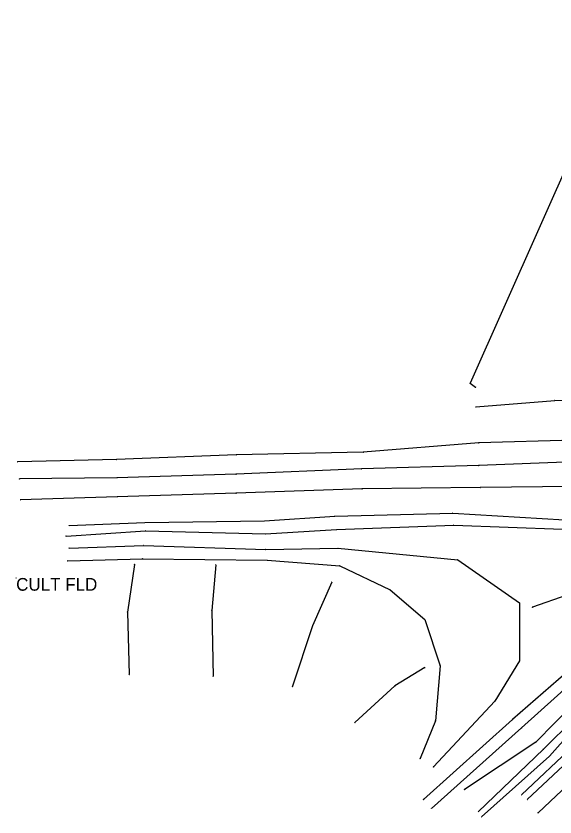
# Model space of a CAD drawing. Extents: x 1419505 to 1434054, y 1956910 to 1968644.
# Drawn here: x 1432317.2 to 1432529.3, y 1967106.7 to 1967422 of the extents above; entities that cross this region are included whole.
import ezdxf

# ---------------------------------------------------------------- set-up
doc = ezdxf.new("R2010")
doc.units = 0
for name, color, linetype in [('S_BREAKLINE', 7, 'Continuous'), ('S_DITCHLINE', 7, 'Continuous'), ('S_EDGE_PAVEMENT', 7, 'Continuous'), ('S_GRAVEL_ROAD', 7, 'Continuous'), ('S_GRD_PT_SYM', 7, 'Continuous'), ('S_MSC_PT_SYM', 7, 'Continuous'), ('S_PAVEMENT_CROWN', 7, 'Continuous'), ('S_RDW_PT_SYM', 7, 'Continuous'), ('S_SHOULDER', 7, 'Continuous'), ('S_SURVEY_TEXT_ANNOT', 7, 'Continuous')]:
    doc.layers.add(name, color=color, linetype=linetype)

msp = doc.modelspace()

# ---------------------------------------------------------------- linework, layer by layer
at = {"layer": 'S_BREAKLINE'}
for p, q in [((1432560.0563, 1967422.0191), (1432495.9372, 1967277.4358)), ((1432495.9372, 1967277.4358), (1432498.0663, 1967275.9717)), ((1432498.2003, 1967268.1522), (1432529.1903, 1967270.6804)), ((1432529.1903, 1967270.6804), (1432576.7534, 1967271.8494)), ((1432414.9679, 1967223.2913), (1432442.6717, 1967225.1514)), ((1432442.6717, 1967225.1514), (1432489.0497, 1967226.2985)), ((1432489.0497, 1967226.2985), (1432533.0896, 1967223.6753)), ((1432338.1, 1967221.4392), (1432367.8779, 1967222.6233)), ((1432367.8779, 1967222.6233), (1432414.9679, 1967223.2913)), ((1432443.3758, 1967219.8871), (1432489.4507, 1967221.5802)), ((1432489.4507, 1967221.5802), (1432532.2115, 1967219.9741)), ((1432336.8839, 1967217.3089), (1432368.1079, 1967219.3541)), ((1432368.1079, 1967219.3541), (1432415.426, 1967218.132)), ((1432415.426, 1967218.132), (1432443.3758, 1967219.8871)), ((1432338.032, 1967212.5476), (1432367.2998, 1967213.5257)), ((1432367.2998, 1967213.5257), (1432415.45, 1967212.0446)), ((1432415.45, 1967212.0446), (1432443.8868, 1967212.4766)), ((1432443.8868, 1967212.4766), (1432491.0348, 1967207.9533)), ((1432337.5179, 1967207.5113), (1432366.9238, 1967208.3894)), ((1432363.7476, 1967206.1302), (1432361.0204, 1967187.374)), ((1432366.9238, 1967208.3894), (1432416.071, 1967207.7913)), ((1432395.7667, 1967205.9642), (1432394.2956, 1967187.977)), ((1432416.071, 1967207.7913), (1432444.5708, 1967205.5362)), ((1432491.0348, 1967207.9533), (1432515.3074, 1967191.0142)), ((1432444.5708, 1967205.5362), (1432464.4411, 1967196.1946)), ((1432441.4576, 1967199.1618), (1432433.9141, 1967181.9636)), ((1432464.4411, 1967196.1946), (1432478.058, 1967184.4478)), ((1432534.0146, 1967193.9934), (1432520.4247, 1967189.2581)), ((1432515.3074, 1967191.0142), (1432515.3974, 1967168.1538)), ((1432361.0204, 1967187.374), (1432361.7465, 1967162.8484)), ((1432394.2956, 1967187.977), (1432394.7676, 1967162.0754)), ((1432478.058, 1967184.4478), (1432484.1664, 1967166.2686)), ((1432433.9141, 1967181.9636), (1432425.8576, 1967157.8041)), ((1432543.0472, 1967171.614), (1432512.6112, 1967145.0493)), ((1432515.3974, 1967168.1538), (1432505.6408, 1967152.3637)), ((1432545.1023, 1967167.8597), (1432516.1835, 1967141.784)), ((1432478.145, 1967165.5666), (1432466.2952, 1967158.2901)), ((1432484.1664, 1967166.2686), (1432482.3463, 1967144.5862)), ((1432570.1649, 1967166.6427), (1432516.1655, 1967115.4223)), ((1432552.6958, 1967159.5972), (1432527.1482, 1967130.6403)), ((1432466.2952, 1967158.2901), (1432450.5672, 1967143.9662)), ((1432505.6408, 1967152.3637), (1432481.4732, 1967126.4161)), ((1432482.3463, 1967144.5862), (1432476.2009, 1967129.7003)), ((1432512.6112, 1967145.0493), (1432477.531, 1967113.5562)), ((1432516.1835, 1967141.784), (1432480.7232, 1967110.074)), ((1432527.1482, 1967130.6403), (1432500.4474, 1967106.7658))]:
    msp.add_line(p, q, dxfattribs=at)
at = {"layer": 'S_DITCHLINE'}
for p, q in [((1432548.9296, 1967163.9905), (1432521.7968, 1967136.2097)), ((1432551.9218, 1967160.5493), (1432524.851, 1967133.4315)), ((1432521.7968, 1967136.2097), (1432493.642, 1967117.4695)), ((1432524.851, 1967133.4315), (1432499.0664, 1967108.7309))]:
    msp.add_line(p, q, dxfattribs=at)
at = {"layer": 'S_EDGE_PAVEMENT'}
msp.add_line((1432576.4614, 1967159.2652), (1432522.6489, 1967108.3919), dxfattribs=at)
at = {"layer": 'S_GRAVEL_ROAD'}
for p, q in [((1432499.3074, 1967253.9743), (1432453.8754, 1967250.3111)), ((1432541.3131, 1967255.2424), (1432499.3074, 1967253.9743)), ((1432453.8754, 1967250.3111), (1432403.8462, 1967249.317)), ((1432356.7542, 1967247.4569), (1432317.8497, 1967246.5728)), ((1432403.8462, 1967249.317), (1432356.7542, 1967247.4569)), ((1432403.8072, 1967234.126), (1432356.9852, 1967232.7219)), ((1432453.3994, 1967235.8491), (1432403.8072, 1967234.126)), ((1432499.9084, 1967236.4522), (1432453.3994, 1967235.8491)), ((1432540.563, 1967236.9162), (1432499.9084, 1967236.4522)), ((1432356.9852, 1967232.7219), (1432318.8787, 1967231.5618))]:
    msp.add_line(p, q, dxfattribs=at)
at = {"layer": 'S_GRD_PT_SYM'}
for points in [[(1432495.9372, 1967277.4358), (1432495.9372, 1967277.4858), (1432495.9372, 1967277.4358), (1432495.8872, 1967277.4358), (1432495.9372, 1967277.4358), (1432495.9372, 1967277.3858), (1432495.9372, 1967277.4358), (1432495.9872, 1967277.4358)], [(1432498.0663, 1967275.9717), (1432498.0663, 1967276.0217), (1432498.0663, 1967275.9717), (1432498.0163, 1967275.9717), (1432498.0663, 1967275.9717), (1432498.0663, 1967275.9217), (1432498.0663, 1967275.9717), (1432498.1163, 1967275.9717)], [(1432529.1903, 1967270.6804), (1432529.1903, 1967270.7304), (1432529.1903, 1967270.6804), (1432529.1403, 1967270.6804), (1432529.1903, 1967270.6804), (1432529.1903, 1967270.6304), (1432529.1903, 1967270.6804), (1432529.2403, 1967270.6804)], [(1432498.2003, 1967268.1522), (1432498.2003, 1967268.2022), (1432498.2003, 1967268.1522), (1432498.1503, 1967268.1522), (1432498.2003, 1967268.1522), (1432498.2003, 1967268.1022), (1432498.2003, 1967268.1522), (1432498.2503, 1967268.1522)], [(1432442.6717, 1967225.1514), (1432442.6717, 1967225.2014), (1432442.6717, 1967225.1514), (1432442.6217, 1967225.1514), (1432442.6717, 1967225.1514), (1432442.6717, 1967225.1014), (1432442.6717, 1967225.1514), (1432442.7217, 1967225.1514)], [(1432489.0497, 1967226.2985), (1432489.0497, 1967226.3485), (1432489.0497, 1967226.2985), (1432488.9997, 1967226.2985), (1432489.0497, 1967226.2985), (1432489.0497, 1967226.2485), (1432489.0497, 1967226.2985), (1432489.0997, 1967226.2985)], [(1432338.1, 1967221.4392), (1432338.1, 1967221.4892), (1432338.1, 1967221.4392), (1432338.05, 1967221.4392), (1432338.1, 1967221.4392), (1432338.1, 1967221.3892), (1432338.1, 1967221.4392), (1432338.15, 1967221.4392)], [(1432367.8779, 1967222.6233), (1432367.8779, 1967222.6733), (1432367.8779, 1967222.6233), (1432367.8279, 1967222.6233), (1432367.8779, 1967222.6233), (1432367.8779, 1967222.5733), (1432367.8779, 1967222.6233), (1432367.9279, 1967222.6233)], [(1432414.9679, 1967223.2913), (1432414.9679, 1967223.3413), (1432414.9679, 1967223.2913), (1432414.9179, 1967223.2913), (1432414.9679, 1967223.2913), (1432414.9679, 1967223.2413), (1432414.9679, 1967223.2913), (1432415.0179, 1967223.2913)], [(1432489.4507, 1967221.5802), (1432489.4507, 1967221.6302), (1432489.4507, 1967221.5802), (1432489.4007, 1967221.5802), (1432489.4507, 1967221.5802), (1432489.4507, 1967221.5302), (1432489.4507, 1967221.5802), (1432489.5007, 1967221.5802)], [(1432368.1079, 1967219.3541), (1432368.1079, 1967219.4041), (1432368.1079, 1967219.3541), (1432368.0579, 1967219.3541), (1432368.1079, 1967219.3541), (1432368.1079, 1967219.3041), (1432368.1079, 1967219.3541), (1432368.1579, 1967219.3541)], [(1432443.3758, 1967219.8871), (1432443.3758, 1967219.9371), (1432443.3758, 1967219.8871), (1432443.3258, 1967219.8871), (1432443.3758, 1967219.8871), (1432443.3758, 1967219.8371), (1432443.3758, 1967219.8871), (1432443.4258, 1967219.8871)], [(1432336.8839, 1967217.3089), (1432336.8839, 1967217.3589), (1432336.8839, 1967217.3089), (1432336.8339, 1967217.3089), (1432336.8839, 1967217.3089), (1432336.8839, 1967217.2589), (1432336.8839, 1967217.3089), (1432336.9339, 1967217.3089)], [(1432415.426, 1967218.132), (1432415.426, 1967218.182), (1432415.426, 1967218.132), (1432415.376, 1967218.132), (1432415.426, 1967218.132), (1432415.426, 1967218.082), (1432415.426, 1967218.132), (1432415.476, 1967218.132)], [(1432338.032, 1967212.5476), (1432338.032, 1967212.5976), (1432338.032, 1967212.5476), (1432337.982, 1967212.5476), (1432338.032, 1967212.5476), (1432338.032, 1967212.4976), (1432338.032, 1967212.5476), (1432338.082, 1967212.5476)], [(1432367.2998, 1967213.5257), (1432367.2998, 1967213.5757), (1432367.2998, 1967213.5257), (1432367.2498, 1967213.5257), (1432367.2998, 1967213.5257), (1432367.2998, 1967213.4757), (1432367.2998, 1967213.5257), (1432367.3498, 1967213.5257)], [(1432415.45, 1967212.0446), (1432415.45, 1967212.0946), (1432415.45, 1967212.0446), (1432415.4, 1967212.0446), (1432415.45, 1967212.0446), (1432415.45, 1967211.9946), (1432415.45, 1967212.0446), (1432415.5, 1967212.0446)], [(1432443.8868, 1967212.4766), (1432443.8868, 1967212.5266), (1432443.8868, 1967212.4766), (1432443.8368, 1967212.4766), (1432443.8868, 1967212.4766), (1432443.8868, 1967212.4266), (1432443.8868, 1967212.4766), (1432443.9368, 1967212.4766)], [(1432337.5179, 1967207.5113), (1432337.5179, 1967207.5613), (1432337.5179, 1967207.5113), (1432337.4679, 1967207.5113), (1432337.5179, 1967207.5113), (1432337.5179, 1967207.4613), (1432337.5179, 1967207.5113), (1432337.5679, 1967207.5113)], [(1432363.7476, 1967206.1302), (1432363.7476, 1967206.1802), (1432363.7476, 1967206.1302), (1432363.6976, 1967206.1302), (1432363.7476, 1967206.1302), (1432363.7476, 1967206.0802), (1432363.7476, 1967206.1302), (1432363.7976, 1967206.1302)], [(1432366.9238, 1967208.3894), (1432366.9238, 1967208.4394), (1432366.9238, 1967208.3894), (1432366.8738, 1967208.3894), (1432366.9238, 1967208.3894), (1432366.9238, 1967208.3394), (1432366.9238, 1967208.3894), (1432366.9738, 1967208.3894)], [(1432395.7667, 1967205.9642), (1432395.7667, 1967206.0142), (1432395.7667, 1967205.9642), (1432395.7167, 1967205.9642), (1432395.7667, 1967205.9642), (1432395.7667, 1967205.9142), (1432395.7667, 1967205.9642), (1432395.8167, 1967205.9642)], [(1432416.071, 1967207.7913), (1432416.071, 1967207.8413), (1432416.071, 1967207.7913), (1432416.021, 1967207.7913), (1432416.071, 1967207.7913), (1432416.071, 1967207.7413), (1432416.071, 1967207.7913), (1432416.121, 1967207.7913)], [(1432491.0348, 1967207.9533), (1432491.0348, 1967208.0033), (1432491.0348, 1967207.9533), (1432490.9848, 1967207.9533), (1432491.0348, 1967207.9533), (1432491.0348, 1967207.9033), (1432491.0348, 1967207.9533), (1432491.0848, 1967207.9533)], [(1432444.5708, 1967205.5362), (1432444.5708, 1967205.5862), (1432444.5708, 1967205.5362), (1432444.5208, 1967205.5362), (1432444.5708, 1967205.5362), (1432444.5708, 1967205.4862), (1432444.5708, 1967205.5362), (1432444.6208, 1967205.5362)], [(1432441.4576, 1967199.1618), (1432441.4576, 1967199.2118), (1432441.4576, 1967199.1618), (1432441.4076, 1967199.1618), (1432441.4576, 1967199.1618), (1432441.4576, 1967199.1118), (1432441.4576, 1967199.1618), (1432441.5076, 1967199.1618)], [(1432464.4411, 1967196.1946), (1432464.4411, 1967196.2446), (1432464.4411, 1967196.1946), (1432464.3911, 1967196.1946), (1432464.4411, 1967196.1946), (1432464.4411, 1967196.1446), (1432464.4411, 1967196.1946), (1432464.4911, 1967196.1946)], [(1432515.3074, 1967191.0142), (1432515.3074, 1967191.0642), (1432515.3074, 1967191.0142), (1432515.2574, 1967191.0142), (1432515.3074, 1967191.0142), (1432515.3074, 1967190.9642), (1432515.3074, 1967191.0142), (1432515.3574, 1967191.0142)], [(1432361.0204, 1967187.374), (1432361.0204, 1967187.424), (1432361.0204, 1967187.374), (1432360.9704, 1967187.374), (1432361.0204, 1967187.374), (1432361.0204, 1967187.324), (1432361.0204, 1967187.374), (1432361.0704, 1967187.374)], [(1432394.2956, 1967187.977), (1432394.2956, 1967188.027), (1432394.2956, 1967187.977), (1432394.2456, 1967187.977), (1432394.2956, 1967187.977), (1432394.2956, 1967187.927), (1432394.2956, 1967187.977), (1432394.3456, 1967187.977)], [(1432520.4247, 1967189.2581), (1432520.4247, 1967189.3081), (1432520.4247, 1967189.2581), (1432520.3747, 1967189.2581), (1432520.4247, 1967189.2581), (1432520.4247, 1967189.2081), (1432520.4247, 1967189.2581), (1432520.4747, 1967189.2581)], [(1432478.058, 1967184.4478), (1432478.058, 1967184.4978), (1432478.058, 1967184.4478), (1432478.008, 1967184.4478), (1432478.058, 1967184.4478), (1432478.058, 1967184.3978), (1432478.058, 1967184.4478), (1432478.108, 1967184.4478)], [(1432433.9141, 1967181.9636), (1432433.9141, 1967182.0136), (1432433.9141, 1967181.9636), (1432433.8641, 1967181.9636), (1432433.9141, 1967181.9636), (1432433.9141, 1967181.9136), (1432433.9141, 1967181.9636), (1432433.9641, 1967181.9636)], [(1432515.3974, 1967168.1538), (1432515.3974, 1967168.2038), (1432515.3974, 1967168.1538), (1432515.3474, 1967168.1538), (1432515.3974, 1967168.1538), (1432515.3974, 1967168.1038), (1432515.3974, 1967168.1538), (1432515.4474, 1967168.1538)], [(1432478.145, 1967165.5666), (1432478.145, 1967165.6166), (1432478.145, 1967165.5666), (1432478.095, 1967165.5666), (1432478.145, 1967165.5666), (1432478.145, 1967165.5166), (1432478.145, 1967165.5666), (1432478.195, 1967165.5666)], [(1432484.1664, 1967166.2686), (1432484.1664, 1967166.3186), (1432484.1664, 1967166.2686), (1432484.1164, 1967166.2686), (1432484.1664, 1967166.2686), (1432484.1664, 1967166.2186), (1432484.1664, 1967166.2686), (1432484.2164, 1967166.2686)], [(1432361.7465, 1967162.8484), (1432361.7465, 1967162.8984), (1432361.7465, 1967162.8484), (1432361.6965, 1967162.8484), (1432361.7465, 1967162.8484), (1432361.7465, 1967162.7984), (1432361.7465, 1967162.8484), (1432361.7965, 1967162.8484)], [(1432394.7676, 1967162.0754), (1432394.7676, 1967162.1254), (1432394.7676, 1967162.0754), (1432394.7176, 1967162.0754), (1432394.7676, 1967162.0754), (1432394.7676, 1967162.0254), (1432394.7676, 1967162.0754), (1432394.8176, 1967162.0754)], [(1432425.8576, 1967157.8041), (1432425.8576, 1967157.8541), (1432425.8576, 1967157.8041), (1432425.8076, 1967157.8041), (1432425.8576, 1967157.8041), (1432425.8576, 1967157.7541), (1432425.8576, 1967157.8041), (1432425.9076, 1967157.8041)], [(1432466.2952, 1967158.2901), (1432466.2952, 1967158.3401), (1432466.2952, 1967158.2901), (1432466.2452, 1967158.2901), (1432466.2952, 1967158.2901), (1432466.2952, 1967158.2401), (1432466.2952, 1967158.2901), (1432466.3452, 1967158.2901)], [(1432505.6408, 1967152.3637), (1432505.6408, 1967152.4137), (1432505.6408, 1967152.3637), (1432505.5908, 1967152.3637), (1432505.6408, 1967152.3637), (1432505.6408, 1967152.3137), (1432505.6408, 1967152.3637), (1432505.6908, 1967152.3637)], [(1432450.5672, 1967143.9662), (1432450.5672, 1967144.0162), (1432450.5672, 1967143.9662), (1432450.5172, 1967143.9662), (1432450.5672, 1967143.9662), (1432450.5672, 1967143.9162), (1432450.5672, 1967143.9662), (1432450.6172, 1967143.9662)], [(1432482.3463, 1967144.5862), (1432482.3463, 1967144.6362), (1432482.3463, 1967144.5862), (1432482.2963, 1967144.5862), (1432482.3463, 1967144.5862), (1432482.3463, 1967144.5362), (1432482.3463, 1967144.5862), (1432482.3963, 1967144.5862)], [(1432512.6112, 1967145.0493), (1432512.6112, 1967145.0993), (1432512.6112, 1967145.0493), (1432512.5612, 1967145.0493), (1432512.6112, 1967145.0493), (1432512.6112, 1967144.9993), (1432512.6112, 1967145.0493), (1432512.6612, 1967145.0493)], [(1432516.1835, 1967141.784), (1432516.1835, 1967141.834), (1432516.1835, 1967141.784), (1432516.1335, 1967141.784), (1432516.1835, 1967141.784), (1432516.1835, 1967141.734), (1432516.1835, 1967141.784), (1432516.2335, 1967141.784)], [(1432521.7968, 1967136.2097), (1432521.7968, 1967136.2597), (1432521.7968, 1967136.2097), (1432521.7468, 1967136.2097), (1432521.7968, 1967136.2097), (1432521.7968, 1967136.1597), (1432521.7968, 1967136.2097), (1432521.8468, 1967136.2097)], [(1432524.851, 1967133.4315), (1432524.851, 1967133.4815), (1432524.851, 1967133.4315), (1432524.801, 1967133.4315), (1432524.851, 1967133.4315), (1432524.851, 1967133.3815), (1432524.851, 1967133.4315), (1432524.901, 1967133.4315)], [(1432527.1482, 1967130.6403), (1432527.1482, 1967130.6903), (1432527.1482, 1967130.6403), (1432527.0982, 1967130.6403), (1432527.1482, 1967130.6403), (1432527.1482, 1967130.5903), (1432527.1482, 1967130.6403), (1432527.1982, 1967130.6403)], [(1432476.2009, 1967129.7003), (1432476.2009, 1967129.7503), (1432476.2009, 1967129.7003), (1432476.1509, 1967129.7003), (1432476.2009, 1967129.7003), (1432476.2009, 1967129.6503), (1432476.2009, 1967129.7003), (1432476.2509, 1967129.7003)], [(1432481.4732, 1967126.4161), (1432481.4732, 1967126.4661), (1432481.4732, 1967126.4161), (1432481.4232, 1967126.4161), (1432481.4732, 1967126.4161), (1432481.4732, 1967126.3661), (1432481.4732, 1967126.4161), (1432481.5232, 1967126.4161)], [(1432493.642, 1967117.4695), (1432493.642, 1967117.5195), (1432493.642, 1967117.4695), (1432493.592, 1967117.4695), (1432493.642, 1967117.4695), (1432493.642, 1967117.4195), (1432493.642, 1967117.4695), (1432493.692, 1967117.4695)], [(1432516.1655, 1967115.4223), (1432516.1655, 1967115.4723), (1432516.1655, 1967115.4223), (1432516.1155, 1967115.4223), (1432516.1655, 1967115.4223), (1432516.1655, 1967115.3723), (1432516.1655, 1967115.4223), (1432516.2155, 1967115.4223)], [(1432477.531, 1967113.5562), (1432477.531, 1967113.6062), (1432477.531, 1967113.5562), (1432477.481, 1967113.5562), (1432477.531, 1967113.5562), (1432477.531, 1967113.5062), (1432477.531, 1967113.5562), (1432477.581, 1967113.5562)], [(1432480.7232, 1967110.074), (1432480.7232, 1967110.124), (1432480.7232, 1967110.074), (1432480.6732, 1967110.074), (1432480.7232, 1967110.074), (1432480.7232, 1967110.024), (1432480.7232, 1967110.074), (1432480.7732, 1967110.074)], [(1432499.0664, 1967108.7309), (1432499.0664, 1967108.7809), (1432499.0664, 1967108.7309), (1432499.0164, 1967108.7309), (1432499.0664, 1967108.7309), (1432499.0664, 1967108.6809), (1432499.0664, 1967108.7309), (1432499.1164, 1967108.7309)], [(1432500.4474, 1967106.7658), (1432500.4474, 1967106.8158), (1432500.4474, 1967106.7658), (1432500.3974, 1967106.7658), (1432500.4474, 1967106.7658), (1432500.4474, 1967106.7158), (1432500.4474, 1967106.7658), (1432500.4974, 1967106.7658)]]:
    msp.add_lwpolyline(points, dxfattribs=at)
at = {"layer": 'S_MSC_PT_SYM'}
msp.add_lwpolyline([(1432317.2226, 1967200.7879), (1432317.2226, 1967200.8379), (1432317.2226, 1967200.7879), (1432317.1726, 1967200.7879), (1432317.2226, 1967200.7879), (1432317.2226, 1967200.7379), (1432317.2226, 1967200.7879), (1432317.2726, 1967200.7879)], dxfattribs=at)
at = {"layer": 'S_PAVEMENT_CROWN'}
for p, q in [((1432453.2214, 1967243.7596), (1432403.7692, 1967241.6505)), ((1432499.3144, 1967245.0467), (1432453.2214, 1967243.7596)), ((1432540.352, 1967246.6358), (1432499.3144, 1967245.0467)), ((1432403.7692, 1967241.6505), (1432356.8602, 1967240.1854)), ((1432356.8602, 1967240.1854), (1432318.5777, 1967239.7704))]:
    msp.add_line(p, q, dxfattribs=at)
at = {"layer": 'S_RDW_PT_SYM'}
for points in [[(1432499.3074, 1967253.9743), (1432499.3074, 1967254.0243), (1432499.3074, 1967253.9743), (1432499.2574, 1967253.9743), (1432499.3074, 1967253.9743), (1432499.3074, 1967253.9243), (1432499.3074, 1967253.9743), (1432499.3574, 1967253.9743)], [(1432453.8754, 1967250.3111), (1432453.8754, 1967250.3611), (1432453.8754, 1967250.3111), (1432453.8254, 1967250.3111), (1432453.8754, 1967250.3111), (1432453.8754, 1967250.2611), (1432453.8754, 1967250.3111), (1432453.9254, 1967250.3111)], [(1432356.7542, 1967247.4569), (1432356.7542, 1967247.5069), (1432356.7542, 1967247.4569), (1432356.7042, 1967247.4569), (1432356.7542, 1967247.4569), (1432356.7542, 1967247.4069), (1432356.7542, 1967247.4569), (1432356.8042, 1967247.4569)], [(1432403.8462, 1967249.317), (1432403.8462, 1967249.367), (1432403.8462, 1967249.317), (1432403.7962, 1967249.317), (1432403.8462, 1967249.317), (1432403.8462, 1967249.267), (1432403.8462, 1967249.317), (1432403.8962, 1967249.317)], [(1432317.8497, 1967246.5728), (1432317.8497, 1967246.6228), (1432317.8497, 1967246.5728), (1432317.7997, 1967246.5728), (1432317.8497, 1967246.5728), (1432317.8497, 1967246.5228), (1432317.8497, 1967246.5728), (1432317.8997, 1967246.5728)], [(1432453.2214, 1967243.7596), (1432453.2214, 1967243.8096), (1432453.2214, 1967243.7596), (1432453.1714, 1967243.7596), (1432453.2214, 1967243.7596), (1432453.2214, 1967243.7096), (1432453.2214, 1967243.7596), (1432453.2714, 1967243.7596)], [(1432499.3144, 1967245.0467), (1432499.3144, 1967245.0967), (1432499.3144, 1967245.0467), (1432499.2644, 1967245.0467), (1432499.3144, 1967245.0467), (1432499.3144, 1967244.9967), (1432499.3144, 1967245.0467), (1432499.3644, 1967245.0467)], [(1432403.7692, 1967241.6505), (1432403.7692, 1967241.7005), (1432403.7692, 1967241.6505), (1432403.7192, 1967241.6505), (1432403.7692, 1967241.6505), (1432403.7692, 1967241.6005), (1432403.7692, 1967241.6505), (1432403.8192, 1967241.6505)], [(1432318.5777, 1967239.7704), (1432318.5777, 1967239.8204), (1432318.5777, 1967239.7704), (1432318.5277, 1967239.7704), (1432318.5777, 1967239.7704), (1432318.5777, 1967239.7204), (1432318.5777, 1967239.7704), (1432318.6277, 1967239.7704)], [(1432356.8602, 1967240.1854), (1432356.8602, 1967240.2354), (1432356.8602, 1967240.1854), (1432356.8102, 1967240.1854), (1432356.8602, 1967240.1854), (1432356.8602, 1967240.1354), (1432356.8602, 1967240.1854), (1432356.9102, 1967240.1854)], [(1432403.8072, 1967234.126), (1432403.8072, 1967234.176), (1432403.8072, 1967234.126), (1432403.7572, 1967234.126), (1432403.8072, 1967234.126), (1432403.8072, 1967234.076), (1432403.8072, 1967234.126), (1432403.8572, 1967234.126)], [(1432453.3994, 1967235.8491), (1432453.3994, 1967235.8991), (1432453.3994, 1967235.8491), (1432453.3494, 1967235.8491), (1432453.3994, 1967235.8491), (1432453.3994, 1967235.7991), (1432453.3994, 1967235.8491), (1432453.4494, 1967235.8491)], [(1432499.9084, 1967236.4522), (1432499.9084, 1967236.5022), (1432499.9084, 1967236.4522), (1432499.8584, 1967236.4522), (1432499.9084, 1967236.4522), (1432499.9084, 1967236.4022), (1432499.9084, 1967236.4522), (1432499.9584, 1967236.4522)], [(1432318.8787, 1967231.5618), (1432318.8787, 1967231.6118), (1432318.8787, 1967231.5618), (1432318.8287, 1967231.5618), (1432318.8787, 1967231.5618), (1432318.8787, 1967231.5118), (1432318.8787, 1967231.5618), (1432318.9287, 1967231.5618)], [(1432356.9852, 1967232.7219), (1432356.9852, 1967232.7719), (1432356.9852, 1967232.7219), (1432356.9352, 1967232.7219), (1432356.9852, 1967232.7219), (1432356.9852, 1967232.6719), (1432356.9852, 1967232.7219), (1432357.0352, 1967232.7219)], [(1432518.4176, 1967113.5832), (1432518.4176, 1967113.6332), (1432518.4176, 1967113.5832), (1432518.3676, 1967113.5832), (1432518.4176, 1967113.5832), (1432518.4176, 1967113.5332), (1432518.4176, 1967113.5832), (1432518.4676, 1967113.5832)], [(1432522.6489, 1967108.3919), (1432522.6489, 1967108.4419), (1432522.6489, 1967108.3919), (1432522.5989, 1967108.3919), (1432522.6489, 1967108.3919), (1432522.6489, 1967108.3419), (1432522.6489, 1967108.3919), (1432522.6989, 1967108.3919)]]:
    msp.add_lwpolyline(points, dxfattribs=at)
at = {"layer": 'S_SHOULDER'}
msp.add_line((1432572.5401, 1967164.7465), (1432518.4176, 1967113.5832), dxfattribs=at)

# ---------------------------------------------------------------- texts
at = {"layer": 'S_SURVEY_TEXT_ANNOT'}
msp.add_text('CULT FLD', height=5, dxfattribs=at).set_placement((1432317.2226, 1967195.7879))

doc.saveas('drawing.dxf')
